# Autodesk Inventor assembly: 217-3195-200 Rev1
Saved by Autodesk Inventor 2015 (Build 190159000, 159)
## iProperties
Created: 2014-11
Part Number: 217-3195-200 Rev1
Document SubType Name: Assembly
Designer: User
Author: User
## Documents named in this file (4)
- C:\Users\User\Documents\Inventor\217-3195-200 Rev1.iam
- C:\Users\User\Documents\Inventor\217-3195-010 Rev1.ipt
- C:\Users\User\Documents\Inventor\217-2778-NCQ8A075-050M_1032_Nut_90545A111.ipt
- C:\Users\User\Documents\Inventor\91251A107_91251A107.ipt
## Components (5 placed, 5 different names)
1. 217-3195-010 Rev1_104
2. 217-3195-010 Rev1_105
3. 217-2778-NCQ8A075-050M_1032_Nut_90545A111_106
4. 91251A107_91251A107_107
5. 91251A107_91251A107_108
